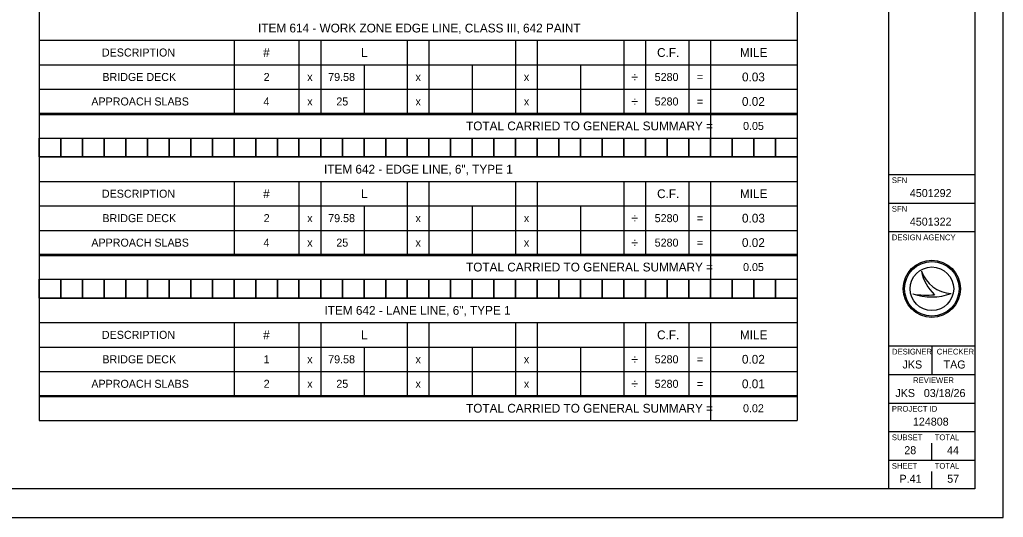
# Model space of a CAD drawing. Extents: x 0 to 34, y 0 to 22.
# Drawn here: x 16.8 to 34, y 0 to 8.71 of the extents above; entities that cross this region are included whole.
import ezdxf

# ---------------------------------------------------------------- set-up
doc = ezdxf.new("R2010")
doc.units = 0
for name, color, linetype in [('SH_Border', 7, 'Continuous'), ('SH_Cut_Line', 7, 'Continuous'), ('SH_Data', 7, 'Continuous'), ('SH_Text', 7, 'Continuous')]:
    doc.layers.add(name, color=color, linetype=linetype)

msp = doc.modelspace()

# ---------------------------------------------------------------- linework, layer by layer
at = {"layer": 'SH_Border'}
for p, q in [((32, 0.5), (32, 21.5)), ((32, 6), (33.5, 6)), ((32, 5.5), (33.5, 5.5)), ((32, 5), (33.5, 5)), ((32, 3), (33.5, 3)), ((32.75, 3), (32.75, 2.5)), ((32, 2.5), (33.5, 2.5)), ((32, 2), (33.5, 2)), ((32, 1.5), (33.5, 1.5)), ((32, 1), (33.5, 1))]:
    msp.add_line(p, q, dxfattribs=at)
msp.add_lwpolyline([(1.5, 21.5), (33.5, 21.5), (33.5, 0.5), (1.5, 0.5)], close=True, dxfattribs=at)
at = {"layer": 'SH_Cut_Line'}
msp.add_lwpolyline([(0, 0), (34, 0), (34, 22), (0, 22)], close=True, dxfattribs=at)
at = {"layer": 'SH_Data'}
for p, q in [((32.75, 5.675), (32.75, 5.675)), ((32.75, 5.175), (32.75, 5.175)), ((32.567, 4.31), (32.567, 4.31)), ((32.75, 4), (32.75, 4)), ((32.417, 3.91), (32.417, 3.91)), ((33.087, 3.919), (33.087, 3.919)), ((32.75, 1), (32.75, 1.3)), ((32.75, 0.5), (32.75, 0.8)), ((32.375, 0.675), (32.375, 0.675))]:
    msp.add_line(p, q, dxfattribs=at)
for radius in [0.5, 0.477, 0.477, 0.382]:
    msp.add_circle((32.75, 4), radius, dxfattribs=at)
for centre, radius, start, end in [((33.116, 4.498), 0.58, 198.9257, 198.9319), ((33.347, 4.47), 0.796, 191.6379, 191.6421), ((33.116, 4.498), 0.58, 198.9319, 267.1657), ((33.347, 4.47), 0.796, 191.6421, 226.0947), ((32.739, 4.87), 1.013, 251.4576, 290.0832), ((32.648, 5.154), 1.266, 259.4964, 259.4995), ((32.739, 4.87), 1.013, 251.4527, 251.4576), ((32.648, 5.154), 1.266, 259.4995, 276.6672)]:
    msp.add_arc(centre, radius, start, end, dxfattribs=at)
at = {"layer": 'SH_Text'}
for p, q in [((17.135, 9.546), (17.135, 7.053)), ((30.394, 9.546), (30.394, 7.053)), ((17.135, 8.349), (30.394, 8.349)), ((20.545, 8.349), (20.545, 7.075)), ((21.681, 8.349), (21.681, 7.075)), ((22.06, 8.349), (22.06, 7.075)), ((23.575, 8.349), (23.575, 7.075)), ((23.954, 8.349), (23.954, 7.075)), ((25.47, 8.349), (25.47, 7.075)), ((25.848, 8.349), (25.848, 7.075)), ((27.364, 8.349), (27.364, 7.075)), ((27.743, 8.349), (27.743, 7.075)), ((28.5, 8.349), (28.5, 7.075)), ((28.879, 8.349), (28.879, 7.075)), ((17.135, 7.921), (30.394, 7.921)), ((22.818, 7.921), (22.818, 7.075)), ((24.712, 7.921), (24.712, 7.075)), ((26.606, 7.921), (26.606, 7.075)), ((17.135, 7.493), (30.394, 7.493)), ((17.135, 7.075), (30.394, 7.075)), ((17.135, 7.075), (17.135, 4.583)), ((30.394, 7.075), (30.394, 4.583)), ((17.135, 7.053), (30.394, 7.053)), ((28.879, 7.053), (28.879, 6.636)), ((17.135, 6.636), (30.394, 6.636)), ((17.135, 6.307), (30.394, 6.307)), ((17.135, 5.878), (30.394, 5.878)), ((20.545, 5.878), (20.545, 4.605)), ((21.681, 5.878), (21.681, 4.605)), ((22.06, 5.878), (22.06, 4.605)), ((23.575, 5.878), (23.575, 4.605)), ((23.954, 5.878), (23.954, 4.605)), ((25.47, 5.878), (25.47, 4.605)), ((25.848, 5.878), (25.848, 4.605)), ((27.364, 5.878), (27.364, 4.605)), ((27.743, 5.878), (27.743, 4.605)), ((28.5, 5.878), (28.5, 4.605)), ((28.879, 5.878), (28.879, 4.605)), ((17.135, 5.45), (30.394, 5.45)), ((22.818, 5.45), (22.818, 4.605)), ((24.712, 5.45), (24.712, 4.605)), ((26.606, 5.45), (26.606, 4.605)), ((17.135, 5.022), (30.394, 5.022)), ((17.135, 4.605), (30.394, 4.605)), ((17.135, 4.605), (17.135, 2.112)), ((17.135, 4.583), (30.394, 4.583)), ((28.879, 4.583), (28.879, 4.166)), ((30.394, 4.605), (30.394, 2.112)), ((17.135, 4.166), (30.394, 4.166)), ((17.135, 3.836), (30.394, 3.836)), ((17.135, 3.408), (30.394, 3.408)), ((20.545, 3.408), (20.545, 2.134)), ((21.681, 3.408), (21.681, 2.134)), ((22.06, 3.408), (22.06, 2.134)), ((23.575, 3.408), (23.575, 2.134)), ((23.954, 3.408), (23.954, 2.134)), ((25.47, 3.408), (25.47, 2.134)), ((25.848, 3.408), (25.848, 2.134)), ((27.364, 3.408), (27.364, 2.134)), ((27.743, 3.408), (27.743, 2.134)), ((28.5, 3.408), (28.5, 2.134)), ((28.879, 3.408), (28.879, 2.134)), ((17.135, 2.98), (30.394, 2.98)), ((22.818, 2.98), (22.818, 2.134)), ((24.712, 2.98), (24.712, 2.134)), ((26.606, 2.98), (26.606, 2.134)), ((17.135, 2.551), (30.394, 2.551)), ((17.135, 2.134), (30.394, 2.134)), ((17.135, 2.134), (17.135, 1.695)), ((17.135, 2.112), (30.394, 2.112)), ((28.879, 2.112), (28.879, 1.695)), ((30.394, 2.134), (30.394, 1.695)), ((17.135, 1.695), (30.394, 1.695))]:
    msp.add_line(p, q, dxfattribs=at)
for points in [[(17.135, 6.636), (17.514, 6.636), (17.514, 6.307), (17.135, 6.307)], [(17.514, 6.636), (17.893, 6.636), (17.893, 6.307), (17.514, 6.307)], [(17.893, 6.636), (18.272, 6.636), (18.272, 6.307), (17.893, 6.307)], [(18.272, 6.636), (18.651, 6.636), (18.651, 6.307), (18.272, 6.307)], [(18.651, 6.636), (19.03, 6.636), (19.03, 6.307), (18.651, 6.307)], [(19.03, 6.636), (19.408, 6.636), (19.408, 6.307), (19.03, 6.307)], [(19.408, 6.636), (19.787, 6.636), (19.787, 6.307), (19.408, 6.307)], [(19.787, 6.636), (20.166, 6.636), (20.166, 6.307), (19.787, 6.307)], [(20.166, 6.636), (20.545, 6.636), (20.545, 6.307), (20.166, 6.307)], [(20.545, 6.636), (20.924, 6.636), (20.924, 6.307), (20.545, 6.307)], [(20.924, 6.636), (21.303, 6.636), (21.303, 6.307), (20.924, 6.307)], [(21.303, 6.636), (21.681, 6.636), (21.681, 6.307), (21.303, 6.307)], [(21.681, 6.636), (22.06, 6.636), (22.06, 6.307), (21.681, 6.307)], [(22.06, 6.636), (22.439, 6.636), (22.439, 6.307), (22.06, 6.307)], [(22.439, 6.636), (22.818, 6.636), (22.818, 6.307), (22.439, 6.307)], [(22.818, 6.636), (23.197, 6.636), (23.197, 6.307), (22.818, 6.307)], [(23.197, 6.636), (23.575, 6.636), (23.575, 6.307), (23.197, 6.307)], [(23.575, 6.636), (23.954, 6.636), (23.954, 6.307), (23.575, 6.307)], [(23.954, 6.636), (24.333, 6.636), (24.333, 6.307), (23.954, 6.307)], [(24.333, 6.636), (24.712, 6.636), (24.712, 6.307), (24.333, 6.307)], [(24.712, 6.636), (25.091, 6.636), (25.091, 6.307), (24.712, 6.307)], [(25.091, 6.636), (25.47, 6.636), (25.47, 6.307), (25.091, 6.307)], [(25.47, 6.636), (25.848, 6.636), (25.848, 6.307), (25.47, 6.307)], [(25.848, 6.636), (26.227, 6.636), (26.227, 6.307), (25.848, 6.307)], [(26.227, 6.636), (26.606, 6.636), (26.606, 6.307), (26.227, 6.307)], [(26.606, 6.636), (26.985, 6.636), (26.985, 6.307), (26.606, 6.307)], [(26.985, 6.636), (27.364, 6.636), (27.364, 6.307), (26.985, 6.307)], [(27.364, 6.636), (27.743, 6.636), (27.743, 6.307), (27.364, 6.307)], [(27.743, 6.636), (28.121, 6.636), (28.121, 6.307), (27.743, 6.307)], [(28.121, 6.636), (28.5, 6.636), (28.5, 6.307), (28.121, 6.307)], [(28.5, 6.636), (28.879, 6.636), (28.879, 6.307), (28.5, 6.307)], [(28.879, 6.636), (29.258, 6.636), (29.258, 6.307), (28.879, 6.307)], [(29.258, 6.636), (29.637, 6.636), (29.637, 6.307), (29.258, 6.307)], [(29.637, 6.636), (30.016, 6.636), (30.016, 6.307), (29.637, 6.307)], [(30.016, 6.636), (30.394, 6.636), (30.394, 6.307), (30.016, 6.307)], [(17.135, 4.166), (17.514, 4.166), (17.514, 3.836), (17.135, 3.836)], [(17.514, 4.166), (17.893, 4.166), (17.893, 3.836), (17.514, 3.836)], [(17.893, 4.166), (18.272, 4.166), (18.272, 3.836), (17.893, 3.836)], [(18.272, 4.166), (18.651, 4.166), (18.651, 3.836), (18.272, 3.836)], [(18.651, 4.166), (19.03, 4.166), (19.03, 3.836), (18.651, 3.836)], [(19.03, 4.166), (19.408, 4.166), (19.408, 3.836), (19.03, 3.836)], [(19.408, 4.166), (19.787, 4.166), (19.787, 3.836), (19.408, 3.836)], [(19.787, 4.166), (20.166, 4.166), (20.166, 3.836), (19.787, 3.836)], [(20.166, 4.166), (20.545, 4.166), (20.545, 3.836), (20.166, 3.836)], [(20.545, 4.166), (20.924, 4.166), (20.924, 3.836), (20.545, 3.836)], [(20.924, 4.166), (21.303, 4.166), (21.303, 3.836), (20.924, 3.836)], [(21.303, 4.166), (21.681, 4.166), (21.681, 3.836), (21.303, 3.836)], [(21.681, 4.166), (22.06, 4.166), (22.06, 3.836), (21.681, 3.836)], [(22.06, 4.166), (22.439, 4.166), (22.439, 3.836), (22.06, 3.836)], [(22.439, 4.166), (22.818, 4.166), (22.818, 3.836), (22.439, 3.836)], [(22.818, 4.166), (23.197, 4.166), (23.197, 3.836), (22.818, 3.836)], [(23.197, 4.166), (23.575, 4.166), (23.575, 3.836), (23.197, 3.836)], [(23.575, 4.166), (23.954, 4.166), (23.954, 3.836), (23.575, 3.836)], [(23.954, 4.166), (24.333, 4.166), (24.333, 3.836), (23.954, 3.836)], [(24.333, 4.166), (24.712, 4.166), (24.712, 3.836), (24.333, 3.836)], [(24.712, 4.166), (25.091, 4.166), (25.091, 3.836), (24.712, 3.836)], [(25.091, 4.166), (25.47, 4.166), (25.47, 3.836), (25.091, 3.836)], [(25.47, 4.166), (25.848, 4.166), (25.848, 3.836), (25.47, 3.836)], [(25.848, 4.166), (26.227, 4.166), (26.227, 3.836), (25.848, 3.836)], [(26.227, 4.166), (26.606, 4.166), (26.606, 3.836), (26.227, 3.836)], [(26.606, 4.166), (26.985, 4.166), (26.985, 3.836), (26.606, 3.836)], [(26.985, 4.166), (27.364, 4.166), (27.364, 3.836), (26.985, 3.836)], [(27.364, 4.166), (27.743, 4.166), (27.743, 3.836), (27.364, 3.836)], [(27.743, 4.166), (28.121, 4.166), (28.121, 3.836), (27.743, 3.836)], [(28.121, 4.166), (28.5, 4.166), (28.5, 3.836), (28.121, 3.836)], [(28.5, 4.166), (28.879, 4.166), (28.879, 3.836), (28.5, 3.836)], [(28.879, 4.166), (29.258, 4.166), (29.258, 3.836), (28.879, 3.836)], [(29.258, 4.166), (29.637, 4.166), (29.637, 3.836), (29.258, 3.836)], [(29.637, 4.166), (30.016, 4.166), (30.016, 3.836), (29.637, 3.836)], [(30.016, 4.166), (30.394, 4.166), (30.394, 3.836), (30.016, 3.836)]]:
    msp.add_lwpolyline(points, close=True, dxfattribs=at)

# ---------------------------------------------------------------- texts
at = {"layer": 'SH_Data'}
for s, height, p in [('SFN', 0.1, (32.05, 5.85)), ('4501292', 0.14, (32.365, 5.605)), ('SFN', 0.1, (32.05, 5.35)), ('4501322', 0.14, (32.365, 5.105)), ('DESIGN AGENCY', 0.1, (32.05, 4.85)), ('DESIGNER', 0.1, (32.054, 2.85)), ('CHECKER', 0.1, (32.835, 2.85)), ('JKS', 0.14, (32.237, 2.605)), ('TAG', 0.14, (32.955, 2.605)), ('REVIEWER', 0.1, (32.422, 2.35)), ('JKS', 0.14, (32.112, 2.105)), ('03/18/26', 0.14, (32.609, 2.105)), ('PROJECT ID', 0.1, (32.05, 1.85)), ('124808', 0.14, (32.419, 1.605)), ('SUBSET', 0.1, (32.05, 1.35)), ('TOTAL', 0.1, (32.8, 1.35)), ('28', 0.14, (32.268, 1.105)), ('44', 0.14, (33.016, 1.105)), ('SHEET', 0.1, (32.05, 0.85)), ('TOTAL', 0.1, (32.8, 0.85)), ('P.41', 0.14, (32.184, 0.605)), ('57', 0.14, (33.018, 0.605))]:
    msp.add_text(s, height=height, dxfattribs=at).set_placement(p)
at = {"layer": 'SH_Text'}
for s, height, p in [('ITEM 614 - WORK ZONE EDGE LINE, CLASS III, 642 PAINT', 0.154, (20.965, 8.486)), ('DESCRIPTION', 0.14, (18.234, 8.065)), ('#', 0.154, (21.054, 8.058)), ('L', 0.154, (22.767, 8.058)), ('C.F.', 0.154, (27.944, 8.058)), ('MILE', 0.154, (29.393, 8.058)), ('BRIDGE DECK', 0.14, (18.242, 7.637)), ('2', 0.14, (21.063, 7.637)), ('x', 0.14, (21.825, 7.637)), ('79.58', 0.14, (22.192, 7.637)), ('x', 0.14, (23.719, 7.637)), ('x', 0.14, (25.614, 7.637)), ('÷', 0.168, (27.491, 7.623)), ('5280', 0.14, (27.902, 7.637)), ('0.03', 0.154, (29.429, 7.63)), ('=', 0.14, (28.64, 7.637)), ('APPROACH SLABS', 0.14, (18.049, 7.208)), ('4', 0.14, (21.06, 7.208)), ('x', 0.14, (21.825, 7.208)), ('25', 0.14, (22.334, 7.208)), ('x', 0.14, (23.719, 7.208)), ('x', 0.14, (25.614, 7.208)), ('÷', 0.168, (27.491, 7.194)), ('5280', 0.14, (27.902, 7.208)), ('=', 0.14, (28.64, 7.208)), ('0.02', 0.154, (29.428, 7.201)), ('TOTAL CARRIED TO GENERAL SUMMARY =', 0.154, (24.603, 6.773)), ('0.05', 0.14, (29.448, 6.78)), ('ITEM 642 - EDGE LINE, 6", TYPE 1', 0.154, (22.119, 6.016)), ('DESCRIPTION', 0.14, (18.234, 5.594)), ('#', 0.154, (21.054, 5.587)), ('L', 0.154, (22.767, 5.587)), ('C.F.', 0.154, (27.944, 5.587)), ('MILE', 0.154, (29.393, 5.587)), ('BRIDGE DECK', 0.14, (18.242, 5.166)), ('2', 0.14, (21.063, 5.166)), ('x', 0.14, (21.825, 5.166)), ('79.58', 0.14, (22.192, 5.166)), ('x', 0.14, (23.719, 5.166)), ('x', 0.14, (25.614, 5.166)), ('÷', 0.168, (27.491, 5.152)), ('5280', 0.14, (27.902, 5.166)), ('=', 0.14, (28.64, 5.166)), ('0.03', 0.154, (29.429, 5.159)), ('APPROACH SLABS', 0.14, (18.049, 4.738)), ('4', 0.14, (21.06, 4.738)), ('x', 0.14, (21.825, 4.738)), ('25', 0.14, (22.334, 4.738)), ('x', 0.14, (23.719, 4.738)), ('x', 0.14, (25.614, 4.738)), ('÷', 0.168, (27.491, 4.724)), ('5280', 0.14, (27.902, 4.738)), ('=', 0.14, (28.64, 4.738)), ('0.02', 0.154, (29.428, 4.731)), ('TOTAL CARRIED TO GENERAL SUMMARY =', 0.154, (24.603, 4.303)), ('0.05', 0.14, (29.448, 4.31)), ('ITEM 642 - LANE LINE, 6", TYPE 1', 0.154, (22.127, 3.545)), ('#', 0.154, (21.054, 3.117)), ('L', 0.154, (22.767, 3.117)), ('C.F.', 0.154, (27.944, 3.117)), ('MILE', 0.154, (29.393, 3.117)), ('DESCRIPTION', 0.14, (18.234, 3.124)), ('BRIDGE DECK', 0.14, (18.242, 2.696)), ('1', 0.14, (21.063, 2.696)), ('x', 0.14, (21.825, 2.696)), ('79.58', 0.14, (22.192, 2.696)), ('x', 0.14, (23.719, 2.696)), ('x', 0.14, (25.614, 2.696)), ('÷', 0.168, (27.491, 2.682)), ('5280', 0.14, (27.902, 2.696)), ('=', 0.14, (28.64, 2.696)), ('0.02', 0.154, (29.428, 2.689)), ('APPROACH SLABS', 0.14, (18.049, 2.267)), ('2', 0.14, (21.063, 2.267)), ('25', 0.14, (22.334, 2.267)), ('5280', 0.14, (27.902, 2.267)), ('0.01', 0.154, (29.428, 2.26)), ('x', 0.14, (21.825, 2.267)), ('x', 0.14, (23.719, 2.267)), ('x', 0.14, (25.614, 2.267)), ('÷', 0.168, (27.491, 2.253)), ('=', 0.14, (28.64, 2.267)), ('TOTAL CARRIED TO GENERAL SUMMARY =', 0.154, (24.603, 1.832)), ('0.02', 0.14, (29.447, 1.839))]:
    msp.add_text(s, height=height, dxfattribs=at).set_placement(p)

doc.saveas('drawing.dxf')
